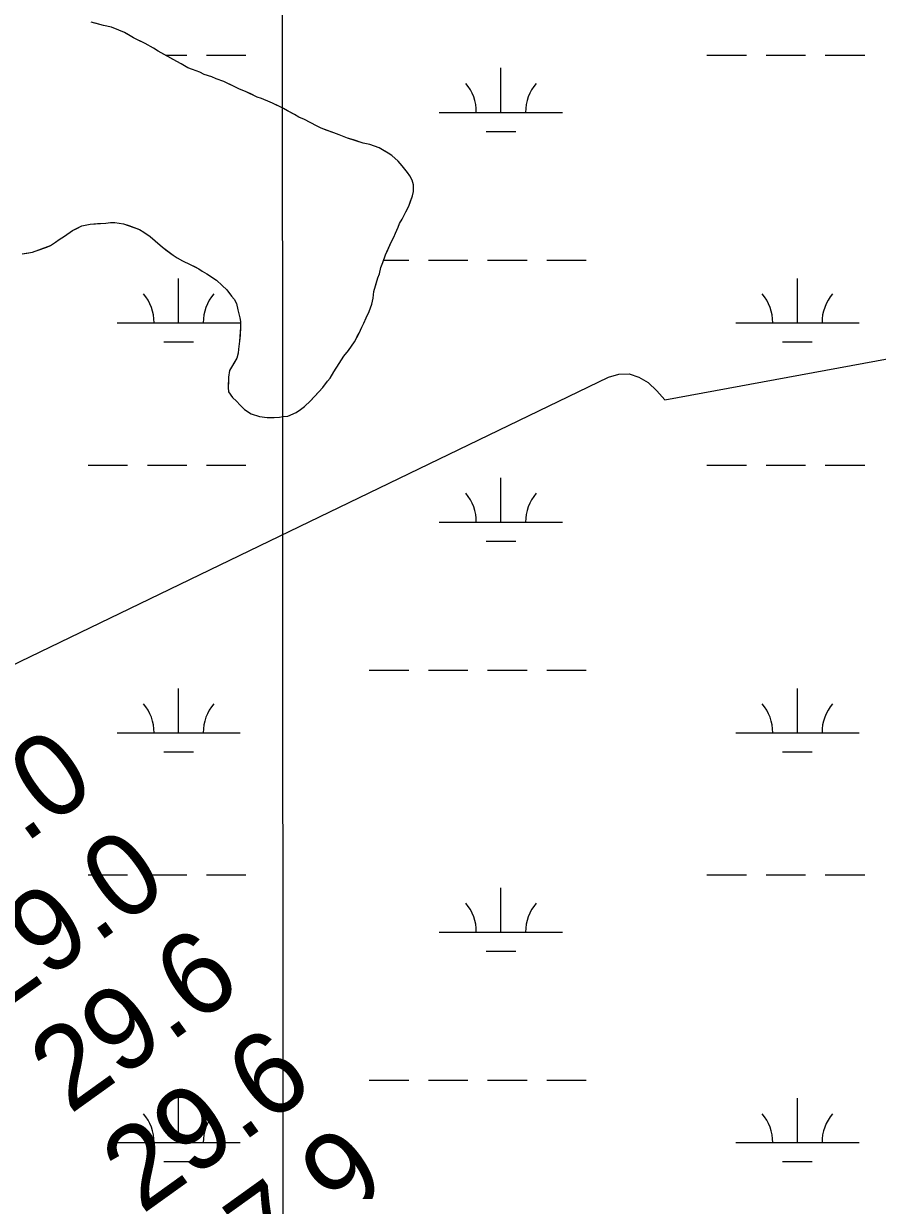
# Model space of a CAD drawing. Extents: x 3281947 to 3319794, y 715894 to 741249.
# Drawn here: x 3296366 to 3297059, y 735444 to 736392 of the extents above; entities that cross this region are included whole.
import ezdxf

# ---------------------------------------------------------------- set-up
doc = ezdxf.new("R2010")
doc.units = 0
for name, color, linetype in [('V-GRID-MAJR', 7, 'Continuous'), ('V-RIVR-EDGE', 7, 'Continuous'), ('V-RIVR-RANG', 7, 'Continuous'), ('V-SITE-VEGE', 7, 'Continuous'), ('V-TOPO-MAJR', 7, 'Continuous'), ('V-TOPO-SHOR', 7, 'Continuous'), ('V-WETL-SWMP', 7, 'Continuous')]:
    doc.layers.add(name, color=color, linetype=linetype)

msp = doc.modelspace()

# ---------------------------------------------------------------- linework, layer by layer
at = {"layer": 'V-GRID-MAJR'}
msp.add_spline([(3296583.23, 721277.09), (3296580.58, 727335.74), (3296577.94, 733397.47), (3296575.29, 739459.23), (3296575.29, 739462.28)], degree=3, dxfattribs=at)
at = {"layer": 'V-RIVR-EDGE'}
msp.add_spline([(3306927.29, 739468.31), (3306926.13, 739467.23), (3306903.71, 739453.6), (3306870.08, 739429.23), (3306847.25, 739417.27), (3306829.83, 739410.68), (3306783.33, 739383.02), (3306752.2, 739364.86), (3306726.05, 739348.76), (3306702.39, 739335.14), (3306684.96, 739324.83), (3306665.87, 739314.93), (3306638.88, 739297.17), (3306600.27, 739272.81), (3306545.47, 739237.3), (3306523.05, 739219.95), (3306470.34, 739190.23), (3306401.43, 739148.13), (3306343.74, 739117.18), (3306258.66, 739071.39), (3306203.04, 739040.44), (3306174.41, 739028.49), (3306163.21, 739023.54), (3306146.6, 739012.81), (3306119.21, 738998.78), (3306082.68, 738977.73), (3306000.93, 738937.32), (3305897.18, 738886.59), (3305874.36, 738874.63), (3305858.59, 738869.28), (3305835.35, 738857.32), (3305801.32, 738839.99), (3305780.99, 738829.68), (3305760.25, 738823.1), (3305753.19, 738818.97), (3305734.92, 738806.17), (3305715.83, 738794.2), (3305680.14, 738778.95), (3305650.28, 738771.15), (3305639.08, 738767.86), (3305612.52, 738755.08), (3305580.99, 738740.65), (3305562.73, 738732.4), (3305541.97, 738719.6), (3305524.13, 738713.02), (3305499.25, 738706.45), (3305484.73, 738701.09), (3305439.9, 738673.85), (3305385.93, 738638.75), (3305341.51, 738613.16), (3305295.02, 738585.09), (3305260.58, 738568.6), (3305238.58, 738557.05), (3305221.15, 738546.73), (3305195.01, 738536.85), (3305174.27, 738531.09), (3305162.66, 738528.22), (3305151.04, 738521.2), (3305133.19, 738510.89), (3305120.74, 738504.7), (3305108.3, 738501.41), (3305096.27, 738496.88), (3305067.63, 738482.03), (3305036.51, 738467.6), (3305009.95, 738456.89), (3304984.64, 738443.69), (3304966.8, 738435.86), (3304935.69, 738426.82), (3304922.41, 738419.81), (3304917, 738414.02), (3304911.19, 738410.3), (3304904.55, 738406.59), (3304892.52, 738401.64), (3304880.49, 738399.19), (3304872.61, 738396.72), (3304863.48, 738393.01), (3304850.2, 738385.17), (3304841.48, 738379.39), (3304833.19, 738377.75), (3304818.27, 738378.2), (3304809.56, 738374.91), (3304778.86, 738365.86), (3304753.14, 738358.05), (3304727.42, 738348.58), (3304707.92, 738338.27), (3304689.23, 738325.88), (3304632.4, 738306.13), (3304574.74, 738288.86), (3304543.63, 738278.57), (3304508.37, 738263.74), (3304471.85, 738248.08), (3304454.85, 738243.15), (3304430.8, 738241.55), (3304416.3, 738244.07), (3304383.98, 738249.54), (3304362.85, 738252.49), (3304345.86, 738250.88), (3304333.83, 738250.49), (3304318.49, 738245.56), (3304302.71, 738236.89), (3304285.68, 738220.77), (3304275.72, 738214.58), (3304263.68, 738208.8), (3304255.79, 738202.61), (3304240.84, 738187.72), (3304227.13, 738174.91), (3304205.53, 738159.21), (3304180.21, 738143.11), (3304166.93, 738134.44), (3304163.18, 738129.06), (3304156.11, 738118.3), (3304146.14, 738111.69), (3304128.72, 738103.44), (3304110.88, 738098.1), (3304071.47, 738083.28), (3303987.25, 738052.4), (3303903.44, 738017.37), (3303874.39, 738005.01), (3303826.68, 737986.89), (3303754.5, 737961.37), (3303700.56, 737937.88), (3303635.84, 737912.34), (3303612.18, 737899.55), (3303591.43, 737889.66), (3303549.95, 737877.74), (3303524.65, 737869.93), (3303506.81, 737863.75), (3303479.01, 737851.8), (3303451.62, 737837.78), (3303415.53, 737823.77), (3303344.58, 737794.11), (3303284.4, 737764.41), (3303261.99, 737752.86), (3303237.91, 737737.17), (3303213.01, 737723.97), (3303186.03, 737709.53), (3303142.47, 737690.16), (3303097.65, 737667.47), (3303032.5, 737639.45), (3302976.49, 737617.2), (3302929.2, 737601.15), (3302876.52, 737583.05), (3302830.47, 737568.65), (3302796.04, 737555.89), (3302747.5, 737537.77), (3302720.11, 737525.41), (3302695.21, 737512.2), (3302675.29, 737499.82), (3302664.09, 737496.95), (3302635.46, 737484.17), (3302576.13, 737459.86), (3302548.74, 737447.08), (3302510.16, 737433.08), (3302457.47, 737413.73), (3302420.96, 737398.07), (3302391.09, 737388.61), (3302329.27, 737363.9), (3302286.53, 737344.93), (3302210.18, 737311.14), (3302137.58, 737284.79), (3302109.37, 737273.25), (3302086.96, 737264.19), (3302049.2, 737245.63), (3302019.74, 737230.78), (3301976.58, 737211.41), (3301950.44, 737201.11), (3301943.39, 737198.23), (3301933.85, 737194.11), (3301894.01, 737176.38), (3301809.36, 737136.8), (3301743.39, 737108.36), (3301680.73, 737080.75), (3301627.61, 737053.94), (3301579.48, 737032.92), (3301552.93, 737023.04), (3301534.26, 737014.79), (3301493.59, 736995.83), (3301411, 736954.58), (3301362.03, 736929.42), (3301310.58, 736905.51), (3301262.86, 736882.42), (3301215.13, 736859.74), (3301178.2, 736842), (3301149.56, 736826.74), (3301101.42, 736800.33), (3301041.66, 736769.39), (3300976.09, 736738.47), (3300927.54, 736714.13), (3300864.46, 736682.38), (3300815.49, 736658.04), (3300740.37, 736620.92), (3300694.72, 736598.24), (3300651.98, 736576.79), (3300615.05, 736559.89), (3300570.64, 736537.62), (3300525.41, 736513.69), (3300478.51, 736490.18), (3300412.11, 736457.6), (3300368.54, 736435.33), (3300334.5, 736417.17), (3300322.47, 736411.81), (3300311.27, 736408.94), (3300299.25, 736406.07), (3300295.52, 736406.08), (3300294.68, 736404.42), (3300294.66, 736396.96), (3300281.39, 736392.43), (3300255.24, 736375.92), (3300190.5, 736346.24), (3300137.8, 736319.43), (3300120.79, 736312.42), (3300104.6, 736304.17), (3300099.2, 736299.21), (3300086.33, 736291.37), (3300046.9, 736269.91), (3299992.95, 736243.1), (3299941.9, 736215.05), (3299871.76, 736177.5), (3299788.33, 736128.8), (3299655.93, 736055.76), (3299580.81, 736015.33), (3299521.04, 735981.49), (3299469.98, 735950.53), (3299434.7, 735930.72), (3299399, 735909.67), (3299352.93, 735884.92), (3299310.19, 735863.05), (3299289.02, 735851.91), (3299266.19, 735838.29), (3299249.17, 735827.14), (3299241.27, 735819.29), (3299240.02, 735816.39), (3299238.36, 735813.08), (3299235.87, 735811.01), (3299230.47, 735809.37), (3299225.08, 735806.89), (3299193.94, 735785.83), (3299175.68, 735777.17), (3299154.93, 735763.96), (3299106.35, 735732.58), (3299056.54, 735703.69), (3299005.48, 735671.9), (3298963.97, 735645.89), (3298895.08, 735610.83), (3298849, 735583.17), (3298814.97, 735563.78), (3298791.31, 735550.16), (3298777.2, 735542.32), (3298768.49, 735541.51), (3298762.28, 735542.35), (3298759.79, 735543.19), (3298757.3, 735541.95), (3298755.22, 735538.23), (3298752.3, 735529.12), (3298741.91, 735517.95), (3298733.18, 735507.61), (3298717.81, 735496.04), (3298693.33, 735486.15), (3298651.82, 735458.9), (3298592.03, 735419.67), (3298532.25, 735380.03), (3298484.1, 735349.89), (3298445.07, 735323.88), (3298407.29, 735299.1), (3298382.8, 735283.41), (3298379.07, 735283.42), (3298372.45, 735288), (3298370.37, 735286.34), (3298373.26, 735281.36), (3298375.32, 735278.46), (3298372.41, 735275.15), (3298357.47, 735264.82), (3298336.29, 735249.12), (3298313.87, 735235.09), (3298289.37, 735216.5), (3298260.31, 735195.84), (3298236.64, 735177.25), (3298208.4, 735155.77), (3298183.07, 735137.18), (3298161.48, 735121.89), (3298140.29, 735103.3), (3298125.34, 735088.83), (3298116.19, 735078.9), (3298113.69, 735074.35), (3298097.08, 735060.71), (3298092.52, 735061.14), (3298082.55, 735052.04), (3298053.07, 735030.98), (3298015.7, 735004.13), (3297985.4, 734984.31), (3297950.93, 734959.52), (3297922.28, 734938.87), (3297903.6, 734926.48), (3297899.03, 734921.93), (3297888.64, 734910.35), (3297879.91, 734901.26), (3297866.21, 734893.42), (3297848.79, 734885.58), (3297830.51, 734869.46), (3297800.18, 734841.77), (3297778.17, 734825.24), (3297773.18, 734817.38), (3297767.79, 734817.39), (3297757.83, 734811.2), (3297737.07, 734797.16), (3297708.83, 734775.26), (3297691.81, 734762.04), (3297668.97, 734745.93), (3297649.04, 734731.89), (3297632.43, 734721.57), (3297622.89, 734718.28), (3297613.35, 734713.74), (3297603.79, 734704.23), (3297598.38, 734695.54), (3297582.6, 734681.07), (3297559.33, 734659.16), (3297519.87, 734623.61), (3297489.97, 734601.31), (3297462.56, 734580.65), (3297445.53, 734565.77), (3297435.15, 734559.16), (3297418.13, 734548.84), (3297407.33, 734538.51), (3297396.95, 734528.59), (3297386.13, 734512.86), (3297377.81, 734501.69), (3297353.31, 734483.52), (3297326.32, 734462.03), (3297292.25, 734431.44), (3297270.24, 734412.43), (3297255.3, 734402.93), (3297250.32, 734400.46), (3297246.57, 734394.25), (3297246.14, 734389.69), (3297243.65, 734387.63), (3297231.61, 734377.71), (3297218.32, 734366.96), (3297207.51, 734355.39), (3297200.86, 734347.11), (3297196.7, 734340.08), (3297165.13, 734311.97), (3297099.06, 734245.4), (3297065.41, 734212.74), (3297040.06, 734188.35), (3297027.6, 734178.43), (3297002.26, 734152.8), (3296989.36, 734134.59), (3296962.77, 734110.2)], degree=3, dxfattribs=at)
at = {"layer": 'V-SITE-VEGE'}
for points in [[(3296455.35, 736379.73), (3296447.98, 736384.02), (3296437.33, 736388.35), (3296431.1, 736389.64), (3296421.02, 736392.48)], [(3296531.02, 736175.21), (3296534.81, 736170.09), (3296536.86, 736167.68), (3296538.89, 736164.07), (3296540, 736158.99), (3296541.68, 736152.42), (3296542.23, 736149.43), (3296542.16, 736144.97), (3296541.38, 736133.67), (3296540.39, 736127.13), (3296540.33, 736123.86), (3296539.08, 736119.71), (3296533.27, 736109.68), (3296532.29, 736104.34), (3296532.16, 736096), (3296532.4, 736092.43), (3296535.6, 736087.91), (3296538.83, 736084.88), (3296541.75, 736081.57), (3296545.27, 736078.23), (3296550.87, 736074.57), (3296557.39, 736072.39), (3296563.63, 736071.69), (3296569.28, 736071.6), (3296573.75, 736071.83), (3296576.74, 736072.38), (3296580.61, 736072.62), (3296587.21, 736075.79), (3296590.82, 736078.11), (3296594.13, 736080.44), (3296598.97, 736085.13), (3296605.63, 736092.47), (3296608.96, 736095.99), (3296612.62, 736100.99), (3296614.74, 736103.63), (3296617.8, 736108.65), (3296623.9, 736118.38), (3296626.03, 736121.32), (3296629.68, 736126.03), (3296634.55, 736133.09), (3296638.24, 736140.18), (3296640.4, 736144.91), (3296642.23, 736148.16), (3296644.09, 736152.59), (3296646.55, 736157.61), (3296648.73, 736163.53), (3296649.7, 736168.58), (3296650.38, 736173.93), (3296653.53, 736184.89), (3296654.77, 736188.15), (3296656.04, 736193.49), (3296657.6, 736197.33), (3296659.78, 736203.55), (3296664.41, 736213.89), (3296666.55, 736218.03), (3296667.8, 736221.28), (3296669.96, 736226.01), (3296671.19, 736228.97), (3296673.33, 736232.51), (3296676.1, 736238.42), (3296678.56, 736243.15), (3296681.67, 736251.43), (3296682.32, 736254.99), (3296682.4, 736260.35), (3296681.27, 736264.24), (3296679.54, 736267.84), (3296677.5, 736270.55), (3296673.12, 736275.98), (3296669.91, 736279.6), (3296664.92, 736284.15), (3296661.97, 736286.28), (3296654.6, 736290.56), (3296646.9, 736293.06), (3296641.56, 736294.34), (3296628.82, 736298.41), (3296622.01, 736300.9), (3296617.87, 736302.75), (3296607.51, 736306.48), (3296604.26, 736308.02), (3296593.93, 736313.54), (3296589.49, 736315.4), (3296585.96, 736317.54), (3296577.1, 736322.44), (3296567.94, 736326.75), (3296559.07, 736330.46), (3296555.52, 736331.71), (3296546.65, 736336.02), (3296540.74, 736338.49), (3296528.62, 736344.34), (3296522.41, 736346.52), (3296518.86, 736348.07), (3296512.64, 736349.95), (3296509.09, 736351.79), (3296503.17, 736353.97), (3296499.33, 736355.52), (3296494.02, 736358.58), (3296490.48, 736360.42), (3296475.43, 736368.99), (3296471.59, 736371.44), (3296464.81, 736375.11), (3296455.35, 736379.73)], [(3296365.07, 736204.32), (3296373.42, 736205.67), (3296388.1, 736211.1), (3296392.01, 736214.02), (3296395.02, 736216.05), (3296399.23, 736218.66), (3296405.85, 736223.32), (3296413.35, 736227.08), (3296420.22, 736228.46), (3296432.75, 736229.45), (3296436.62, 736229.98), (3296440.19, 736229.93), (3296447.32, 736228.92), (3296460.05, 736224.26), (3296463.59, 736222.12), (3296468.89, 736218.46), (3296473, 736215.12), (3296478.88, 736209.97), (3296487.41, 736203.29), (3296490.65, 736201.15), (3296495.07, 736198.7), (3296501.28, 736195.92), (3296508.37, 736192.24), (3296511.02, 736190.41), (3296514.86, 736188.27), (3296522.51, 736183.08), (3296527.21, 736178.84), (3296531.02, 736175.21)]]:
    msp.add_lwpolyline(points, dxfattribs=at)
at = {"layer": 'V-TOPO-MAJR'}
msp.add_lwpolyline([(3295942.71, 735355.63), (3296306.46, 735846.31), (3296840.61, 736104.43), (3296849.12, 736106.72), (3296857.36, 736107.05), (3296865.18, 736104.45), (3296872.73, 736099.9), (3296879.71, 736093.14), (3296886.32, 736086.06), (3297900.2, 736272.8)], dxfattribs=at)
at = {"layer": 'V-TOPO-SHOR'}
for points in [[(3296664.92, 736284.15), (3296661.97, 736286.28), (3296658.73, 736288.11), (3296654.6, 736290.56), (3296646.9, 736293.06), (3296641.56, 736294.34), (3296633.86, 736296.84), (3296628.82, 736298.41), (3296622.01, 736300.9), (3296617.87, 736302.75), (3296611.66, 736304.93), (3296607.51, 736306.48), (3296604.26, 736308.02), (3296598.06, 736311.39), (3296593.93, 736313.54), (3296589.49, 736315.4), (3296585.96, 736317.54), (3296580.35, 736320.6), (3296577.1, 736322.44), (3296573.26, 736324.29), (3296567.94, 736326.75), (3296564.39, 736328.3), (3296559.07, 736330.46), (3296555.52, 736331.71), (3296550.49, 736334.17), (3296546.65, 736336.02), (3296540.74, 736338.49), (3296536.31, 736340.65), (3296528.62, 736344.34), (3296522.41, 736346.52), (3296518.86, 736348.07), (3296512.64, 736349.95), (3296509.09, 736351.79), (3296503.17, 736353.97), (3296499.33, 736355.52), (3296494.02, 736358.58), (3296490.48, 736360.42), (3296485.16, 736363.48), (3296481.33, 736365.63), (3296475.43, 736368.99), (3296471.59, 736371.44), (3296464.81, 736375.11), (3296458.6, 736378.19), (3296455.35, 736379.73), (3296451.22, 736382.18), (3296447.98, 736384.01), (3296443.54, 736385.87), (3296437.33, 736388.35), (3296431.1, 736389.64), (3296424.28, 736391.53)], [(3296440.19, 736229.93), (3296447.32, 736228.92), (3296451.46, 736227.37), (3296460.05, 736224.26), (3296463.59, 736222.12), (3296468.89, 736218.46), (3296473, 736215.12), (3296478.88, 736209.97), (3296482.7, 736206.93), (3296487.41, 736203.29), (3296490.65, 736201.15), (3296495.07, 736198.7), (3296501.28, 736195.92), (3296505.42, 736193.77), (3296508.37, 736192.24), (3296511.02, 736190.41), (3296514.86, 736188.27), (3296519.27, 736185.22), (3296522.51, 736183.08), (3296527.21, 736178.84), (3296531.02, 736175.21), (3296534.81, 736170.09), (3296536.86, 736167.68), (3296538.89, 736164.07), (3296540, 736158.99), (3296541.68, 736152.42), (3296542.23, 736149.43), (3296542.16, 736144.97), (3296541.76, 736138.42), (3296541.38, 736133.67), (3296540.39, 736127.13), (3296540.33, 736123.86), (3296539.08, 736119.71), (3296537.24, 736116.46), (3296535.71, 736113.81), (3296533.27, 736109.68), (3296532.29, 736104.34), (3296532.24, 736101.06), (3296532.16, 736096), (3296532.4, 736092.43), (3296535.6, 736087.91), (3296538.83, 736084.89), (3296541.75, 736081.57), (3296545.27, 736078.23), (3296550.87, 736074.57), (3296557.39, 736072.39), (3296563.63, 736071.69), (3296569.28, 736071.6), (3296573.75, 736071.83), (3296576.74, 736072.38), (3296580.61, 736072.62), (3296587.21, 736075.79), (3296590.82, 736078.11), (3296594.13, 736080.44), (3296598.97, 736085.13), (3296601.69, 736088.06), (3296605.63, 736092.47), (3296608.96, 736095.99), (3296612.62, 736100.99), (3296614.74, 736103.63), (3296617.8, 736108.65), (3296622.07, 736115.43), (3296623.9, 736118.38), (3296626.03, 736121.32), (3296629.68, 736126.03), (3296631.51, 736128.68), (3296634.55, 736133.09), (3296636.7, 736137.23), (3296638.24, 736140.18), (3296640.4, 736144.91), (3296642.23, 736148.16), (3296644.09, 736152.59), (3296646.55, 736157.61), (3296648.73, 736163.53), (3296649.7, 736168.58), (3296650.38, 736173.93), (3296651.95, 736179.26), (3296653.53, 736184.89), (3296654.77, 736188.15), (3296656.04, 736193.49), (3296657.6, 736197.33), (3296659.78, 736203.55), (3296661.63, 736207.69), (3296664.41, 736213.89), (3296666.55, 736218.03), (3296667.8, 736221.28), (3296669.96, 736226.01), (3296671.19, 736228.97), (3296673.33, 736232.51), (3296676.1, 736238.42), (3296678.56, 736243.15), (3296679.8, 736246.4), (3296681.67, 736251.43), (3296682.32, 736254.99), (3296682.4, 736260.35), (3296681.27, 736264.24), (3296679.54, 736267.84), (3296677.5, 736270.55), (3296673.12, 736275.98), (3296669.91, 736279.6), (3296664.92, 736284.15)], [(3296365.07, 736204.32), (3296368.65, 736204.86), (3296373.42, 736205.67), (3296376.42, 736206.82), (3296385.1, 736209.96), (3296388.1, 736211.1), (3296392.01, 736214.02), (3296395.02, 736216.05), (3296399.23, 736218.66), (3296405.85, 736223.32), (3296408.85, 736224.77), (3296413.35, 736227.08), (3296420.22, 736228.46), (3296426.19, 736228.96), (3296432.74, 736229.45), (3296436.62, 736229.98), (3296440.19, 736229.93)]]:
    msp.add_lwpolyline(points, dxfattribs=at)
at = {"layer": 'V-WETL-SWMP'}
for p, q in [((3296481.19, 736365.71), (3296498.53, 736365.71)), ((3296514.53, 736365.71), (3296546.53, 736365.71)), ((3296920.44, 736365.71), (3296952.44, 736365.71)), ((3296968.44, 736365.71), (3297000.44, 736365.71)), ((3297016.44, 736365.71), (3297048.44, 736365.71)), ((3296753.38, 736319.28), (3296753.38, 736355.28)), ((3296703.38, 736319.28), (3296803.38, 736319.28)), ((3296741.38, 736303.84), (3296765.38, 736303.84)), ((3296658.25, 736199.2), (3296678.53, 736199.2)), ((3296694.53, 736199.2), (3296726.53, 736199.2)), ((3296742.53, 736199.2), (3296774.53, 736199.2)), ((3296790.53, 736199.2), (3296822.53, 736199.2)), ((3296491.94, 736148.46), (3296491.94, 736184.46)), ((3296993.85, 736148.46), (3296993.85, 736184.46)), ((3296441.94, 736148.46), (3296541.94, 736148.46)), ((3296943.85, 736148.46), (3297043.85, 736148.46)), ((3296479.94, 736133.03), (3296503.94, 736133.03)), ((3296981.85, 736133.03), (3297005.85, 736133.03)), ((3296418.53, 736033.03), (3296450.53, 736033.03)), ((3296466.53, 736033.03), (3296498.53, 736033.03)), ((3296514.53, 736033.03), (3296546.53, 736033.03)), ((3296920.44, 736033.03), (3296952.44, 736033.03)), ((3296968.44, 736033.03), (3297000.44, 736033.03)), ((3297016.44, 736033.03), (3297048.44, 736033.03)), ((3296753.38, 735986.6), (3296753.38, 736022.6)), ((3296703.38, 735986.6), (3296803.38, 735986.6)), ((3296741.38, 735971.17), (3296765.38, 735971.17)), ((3296646.53, 735866.53), (3296678.53, 735866.53)), ((3296694.53, 735866.53), (3296726.53, 735866.53)), ((3296742.53, 735866.53), (3296774.53, 735866.53)), ((3296790.53, 735866.53), (3296822.53, 735866.53)), ((3296491.94, 735815.79), (3296491.94, 735851.79)), ((3296993.85, 735815.79), (3296993.85, 735851.79)), ((3296441.94, 735815.79), (3296541.94, 735815.79)), ((3296943.85, 735815.79), (3297043.85, 735815.79)), ((3296479.94, 735800.36), (3296503.94, 735800.36)), ((3296981.85, 735800.36), (3297005.85, 735800.36)), ((3296418.53, 735700.36), (3296450.53, 735700.36)), ((3296466.53, 735700.36), (3296498.53, 735700.36)), ((3296514.53, 735700.36), (3296546.53, 735700.36)), ((3296920.44, 735700.36), (3296952.44, 735700.36)), ((3296968.44, 735700.36), (3297000.44, 735700.36)), ((3297016.44, 735700.36), (3297048.44, 735700.36)), ((3296753.38, 735653.93), (3296753.38, 735689.93)), ((3296703.38, 735653.93), (3296803.38, 735653.93)), ((3296741.38, 735638.5), (3296765.38, 735638.5)), ((3296646.53, 735533.86), (3296678.53, 735533.86)), ((3296694.53, 735533.86), (3296726.53, 735533.86)), ((3296742.53, 735533.86), (3296774.53, 735533.86)), ((3296790.53, 735533.86), (3296822.53, 735533.86)), ((3296491.94, 735483.11), (3296491.94, 735519.11)), ((3296993.85, 735483.11), (3296993.85, 735519.11)), ((3296441.94, 735483.11), (3296541.94, 735483.11)), ((3296943.85, 735483.11), (3297043.85, 735483.11)), ((3296479.94, 735467.68), (3296503.94, 735467.68)), ((3296981.85, 735467.68), (3297005.85, 735467.68))]:
    msp.add_line(p, q, dxfattribs=at)
for points in [[(3296532.16, 736096), (3296532.4, 736092.43), (3296535.6, 736087.91), (3296538.83, 736084.88), (3296541.75, 736081.56), (3296545.27, 736078.23), (3296550.87, 736074.57), (3296557.39, 736072.39), (3296563.63, 736071.69), (3296569.28, 736071.6), (3296573.75, 736071.83), (3296576.74, 736072.38), (3296580.61, 736072.62), (3296587.21, 736075.79), (3296590.82, 736078.11), (3296594.13, 736080.44), (3296598.97, 736085.13), (3296605.63, 736092.47), (3296608.96, 736095.99), (3296612.62, 736100.99), (3296614.74, 736103.64), (3296617.8, 736108.65), (3296623.9, 736118.38), (3296626.03, 736121.32), (3296629.68, 736126.03), (3296634.55, 736133.09), (3296638.24, 736140.18), (3296640.4, 736144.91), (3296642.23, 736148.16), (3296644.09, 736152.59), (3296646.55, 736157.61), (3296648.73, 736163.53), (3296649.7, 736168.58), (3296650.38, 736173.93), (3296653.53, 736184.89), (3296654.77, 736188.15), (3296656.05, 736193.49), (3296657.6, 736197.33), (3296659.78, 736203.55), (3296664.41, 736213.9), (3296666.55, 736218.03), (3296667.8, 736221.28), (3296669.96, 736226.01), (3296671.19, 736228.97), (3296673.33, 736232.51), (3296676.1, 736238.42), (3296678.56, 736243.15), (3296681.67, 736251.43), (3296682.32, 736254.99), (3296682.4, 736260.35), (3296681.27, 736264.24), (3296679.54, 736267.84), (3296677.5, 736270.55), (3296673.12, 736275.98), (3296669.91, 736279.6), (3296664.92, 736284.14), (3296661.97, 736286.27), (3296654.6, 736290.56), (3296646.9, 736293.06), (3296641.56, 736294.34), (3296628.82, 736298.41), (3296622.01, 736300.9), (3296617.87, 736302.75), (3296607.51, 736306.48), (3296604.26, 736308.02), (3296593.93, 736313.54), (3296589.49, 736315.4), (3296585.96, 736317.54), (3296577.1, 736322.44), (3296567.94, 736326.75), (3296559.07, 736330.46), (3296555.52, 736331.71), (3296546.65, 736336.02), (3296540.74, 736338.49), (3296528.62, 736344.34), (3296522.41, 736346.52), (3296518.86, 736348.07), (3296512.64, 736349.95), (3296509.09, 736351.79), (3296503.17, 736353.97), (3296499.33, 736355.52), (3296494.02, 736358.58), (3296490.47, 736360.42), (3296475.43, 736368.99), (3296471.6, 736371.44), (3296464.81, 736375.11), (3296455.35, 736379.73), (3296447.98, 736384.01), (3296437.33, 736388.35), (3296431.1, 736389.64), (3296421.02, 736392.47)], [(3296365.07, 736204.32), (3296373.42, 736205.67), (3296388.1, 736211.1), (3296392.01, 736214.02), (3296395.02, 736216.05), (3296399.23, 736218.66), (3296405.85, 736223.32), (3296413.35, 736227.08), (3296420.22, 736228.46), (3296432.74, 736229.45), (3296436.62, 736229.98), (3296440.19, 736229.93), (3296447.32, 736228.92), (3296460.05, 736224.26), (3296463.59, 736222.12), (3296468.89, 736218.46), (3296473, 736215.12), (3296478.88, 736209.97), (3296487.41, 736203.29), (3296490.65, 736201.15), (3296495.07, 736198.7), (3296501.28, 736195.92), (3296508.37, 736192.24), (3296511.02, 736190.41), (3296514.85, 736188.27), (3296522.51, 736183.08), (3296527.21, 736178.84), (3296531.02, 736175.21), (3296534.81, 736170.09), (3296536.86, 736167.68), (3296538.89, 736164.07), (3296540, 736158.99), (3296541.68, 736152.42), (3296542.23, 736149.43), (3296542.16, 736144.97), (3296541.38, 736133.67), (3296540.39, 736127.13), (3296540.34, 736123.86), (3296539.08, 736119.71), (3296533.27, 736109.68), (3296532.29, 736104.34), (3296532.16, 736096)]]:
    msp.add_lwpolyline(points, dxfattribs=at)
for centre, start, end in [((3296698.13, 736319.75), 359.22818, 40.77184), ((3296808.62, 736319.75), 139.22818, 180.77184), ((3296436.7, 736148.94), 359.22818, 40.77184), ((3296547.18, 736148.94), 139.22818, 180.77184), ((3296938.61, 736148.94), 359.22818, 40.77184), ((3297049.09, 736148.94), 139.22818, 180.77184), ((3296698.13, 735987.08), 359.22818, 40.77184), ((3296808.62, 735987.08), 139.22818, 180.77184), ((3296436.7, 735816.26), 359.22818, 40.77184), ((3296547.18, 735816.26), 139.22818, 180.77184), ((3296938.61, 735816.26), 359.22818, 40.77184), ((3297049.09, 735816.26), 139.22818, 180.77184), ((3296698.13, 735654.4), 359.22818, 40.77184), ((3296808.62, 735654.4), 139.22818, 180.77184), ((3296436.7, 735483.59), 359.22818, 40.77184), ((3296547.18, 735483.59), 139.22818, 180.77184), ((3296938.61, 735483.59), 359.22818, 40.77184), ((3297049.09, 735483.59), 139.22818, 180.77184)]:
    msp.add_arc(centre, 35.25, start, end, dxfattribs=at)

# ---------------------------------------------------------------- texts
at = {"layer": 'V-RIVR-RANG'}
for s, p in [('29.0', (3296285.74, 735667.09)), ('29.0', (3296344.27, 735586.01)), ('29.6', (3296403.65, 735505.54)), ('29.6', (3296462.18, 735424.45)), ('27.9', (3296521.99, 735344.29))]:
    msp.add_text(s, height=67, rotation=35.67833, dxfattribs=at).set_placement(p)

doc.saveas('drawing.dxf')
